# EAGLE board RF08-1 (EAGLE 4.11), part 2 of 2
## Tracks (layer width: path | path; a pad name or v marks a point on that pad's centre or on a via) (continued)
DMA09  (via drill 0.61) (continued)
  Top 0.254: v130.17,77.3 130.17,72.22 128.27,72.22 127,70.95 125.73,70.95 DMA8-11.6 | 50.79,18.89 50.79,20.16 49.52,21.43 49.52,23.96 50.79,25.23 50.79,29.05 IC11.10 50.79,31.59 49.52,32.86 49.52,47.46 50.79,48.73 50.79,51.91 IC10.10 50.79,54.45 49.52,55.72 49.52,69.68 50.79,70.95 50.79,74.77 IC9.10 | 50.79,18.89 50.79,8.73 IC12.10 | v197.48,72.22 197.48,39.84 196.21,38.57 196.21,4.28 194.94,3.01 160.65,3.01 v160.65,15.71 | v95.88,13.81 v90.8,18.89 | v50.16,18.89 50.79,18.89
  Bottom 0.254: v130.17,77.3 147.31,77.3 148.59,76.03 IC6.6 151.12,76.03 154.94,72.22 v197.48,72.22 | v160.65,15.71 160.65,18.89 140.97,18.89 138.43,16.35 118.74,16.35 116.2,13.81 v95.88,13.81 | v90.8,18.89 v50.16,18.89
DMA10  (via drill 0.61)
  Top 0.254: IC12.11 53.34,8.73 52.06,10 52.06,23.96 53.34,25.23 53.34,29.05 IC11.11 53.34,31.59 52.06,32.86 52.06,46.83 53.34,48.09 53.34,51.91 IC10.11 53.34,54.45 52.06,55.72 52.06,73.49 53.34,74.77 IC9.11 | v133.98,79.84 133.98,89.37 133.34,90 v133.34,91.91 | v125.09,91.91 123.19,93.81 123.19,98.26 123.82,98.89 v123.82,109.05 | v116.84,109.05 115.56,107.78 v115.56,104.61 | v95.88,103.97 95.25,103.34 v95.25,79.84
  Bottom 0.254: DMA8-11.2 125.73,81.11 126.36,80.48 130.17,80.48 130.81,79.84 v133.98,79.84 147.31,79.84 148.59,81.11 IC6.4 | v125.09,91.91 v133.34,91.91 | v116.84,109.05 v123.82,109.05 | v115.56,104.61 114.93,105.24 104.77,105.24 103.5,103.97 v95.88,103.97 | v95.25,79.84 94.61,80.48 57.14,80.48 56.51,79.84 54.6,79.84 53.34,78.57 53.34,77.3 IC9.11
DMA11  (via drill 0.61)
  Top 0.254: IC12.12 55.88,8.73 55.88,20.16 54.6,21.43 54.6,27.78 55.88,29.05 IC11.12 55.88,31.59 54.6,32.86 54.6,50.63 | 54.6,50.63 55.88,51.91 IC10.12 | 54.6,50.63 54.6,73.49 55.88,74.77 IC9.12 55.88,77.3 v55.88,81.75 | v121.28,81.11 v121.28,78.57 | v146.68,86.19 143.5,89.37 143.5,97.62 138.43,102.7 v138.43,106.52 | v88.9,82.38 v88.9,107.15
  Bottom 0.254: v121.28,78.57 123.19,78.57 DMA8-11.3 | v121.28,81.11 120.01,82.38 107.95,82.38 107.31,81.75 88.9,81.75 | v55.88,81.75 88.9,81.75 | v146.68,86.19 148.59,86.19 IC6.2 | v138.43,106.52 104.77,106.52 104.14,107.15 v88.9,107.15 | 88.9,81.75 v88.9,82.38
DMA-IN\  (via drill 0.61)
  Top 0.254: 17.14,44.92 15.87,43.65 IC19.1 | 17.14,44.92 17.14,71.59 15.87,72.86 IC18.1 | v25.39,10.63 17.14,18.89 17.14,44.92
  Bottom 0.254: 13.33,72.22 13.33,73.49 13.96,73.49 IC18.1 | 13.33,72.22 13.33,70.32 13.96,69.68 20.32,69.68 21.59,70.95 IC18.19 | v25.39,10.63 84.45,10.63 85.72,11.9 IC41.12 | 13.33,72.22 4.44,72.22 4.44,77.94 13.96,87.46 16.51,87.46 21.59,92.54 24.12,92.54 25.39,93.81 33.02,93.81 37.46,98.26 IC15.4
DMA-OUT\  (via drill 0.61)
  Top 0.254: v88.26,32.86 88.26,19.52 93.98,13.81 IC41.9 | v81.28,69.68 81.91,69.05 81.91,55.72 83.18,54.45 85.09,54.45 85.09,39.84 84.45,39.2 79.37,39.2 79.37,38.57 IC17.19
  Bottom 0.254: 75.56,67.78 74.93,68.41 72.39,68.41 IC16.1 | 75.56,67.78 77.47,65.88 IC16.19 | IC17.1 72.39,40.48 73.02,40.48 74.29,39.2 76.2,39.2 77.47,37.94 IC17.19 79.37,37.3 82.55,34.12 86.99,34.12 v88.26,32.86 | 75.56,67.78 77.47,69.68 v81.28,69.68
DONE  (via drill 0.61)
  Top 0.254: v135.88,31.59 135.25,30.95 135.25,19.52 136.52,18.25 IC39.2 | v128.9,33.49 129.53,34.12 129.53,51.27 v128.9,51.91 | v139.69,51.91 140.97,53.18 140.97,88.73 v140.33,89.37 | v144.78,89.37 146.05,90.64 146.05,119.21 144.78,120.48 IC35.9
  Bottom 0.254: v135.88,31.59 133.98,33.49 v128.9,33.49 | v139.69,51.91 v128.9,51.91 | v144.78,89.37 v140.33,89.37
DRV01\  (via drill 0.61)
  Top 0.254: IC10.22 53.34,69.68 53.97,70.32 53.97,74.13 54.6,74.77 54.6,77.3 53.34,78.57 v53.34,80.48 53.34,90 IC9.22 | v99.69,6.82 107.95,15.08 v107.95,74.13 | v97.79,74.13 v97.79,78.57
  Bottom 0.254: v99.69,6.82 85.72,6.82 84.45,5.55 IC41.4 | v107.95,74.13 v97.79,74.13 | v97.79,78.57 95.25,81.11 56.51,81.11 55.88,80.48 v53.34,80.48
DRV23\  (via drill 0.61)
  Top 0.254: IC11.22 53.34,44.29 53.34,32.86 54.6,31.59 54.6,29.05 53.97,28.41 53.97,24.6 53.34,23.96 IC12.22 53.34,21.43 53.34,10.63 v54.6,9.36 | v86.36,10 90.8,5.55 IC41.7
  Bottom 0.254: v86.36,10 55.24,10 v54.6,9.36
EIE  (via drill 0.61)
  Top 0.254: v171.44,6.18 174.62,9.36 INTENB.6 175.25,8.73 175.25,8.09 180.97,8.09 181.61,8.73 181.61,21.43 184.78,24.6 IC33.2
  Bottom 0.254: v171.44,6.18 147.31,6.18 146.05,7.46 IC39.9
ERROR  (via drill 0.61)
  Top 0.254: v142.24,91.91 142.24,41.74 142.87,41.11 142.87,11.9 144.14,10.63 IC39.10 | v156.21,91.91 156.84,92.54 156.84,116.67 156.21,117.31 v156.21,121.75 156.21,125.56 IC37.2
  Bottom 0.254: v156.21,91.91 v142.24,91.91 | v156.21,121.75 173.99,121.75 IC34.6
EXAD0\  (via drill 0.61)
  Top 0.254: v5.71,74.77 5.71,68.41 7.62,66.51 C35L.34
  Bottom 0.254: v5.71,74.77 6.34,74.77 14.6,83.02 IC38.9
EXAD1\
  Top 0.254: IC38.7 15.87,89.37 17.14,90.64 17.14,94.45 16.51,95.08 6.98,95.08 6.98,74.77 6.34,74.13 6.34,70.32 7.62,69.05 C35L.36
EXAD2\
  Top 0.254: IC38.5 14.6,93.18 8.88,87.46 8.88,72.86 7.62,71.59 C35L.38
F.1  (1 unrouted)
  Top 0.254: IC32.8 186.05,43.65 187.32,44.92 187.32,104.61 186.05,105.88 FIELD.3
F.2  (via drill 0.61)
  Top 0.254: v34.28,89.37 34.28,117.94 33.65,118.58 v33.65,127.47 | v179.06,128.11 180.97,126.2 180.97,117.31 183.51,114.77 183.51,110.96 184.78,109.69 FIELD.2 | v197.48,38.57 198.12,39.2 198.12,71.59 198.75,72.22 198.75,74.13 195.58,77.3 195.58,105.24 v196.21,105.88
  Bottom 0.254: v34.28,89.37 27.3,89.37 24.12,86.19 IC38.13 | v33.65,127.47 35.55,129.38 164.46,129.38 165.09,128.74 173.35,128.74 173.99,128.11 v179.06,128.11 | v197.48,38.57 194.94,38.57 194.31,37.94 IC32.11 | v196.21,105.88 194.31,107.78 188.59,107.78 187.32,109.05 186.69,109.05 FIELD.2
F.3  (via drill 0.61)
  Top 0.254: v28.57,131.28 29.21,130.65 29.21,120.48 26.67,117.94 26.67,95.08 23.49,91.91 IC38.15 | v168.91,130.01 170.18,128.74 v170.18,124.93 | v199.38,43.02 199.38,73.49 200.66,74.77 v200.66,97.62
  Bottom 0.254: v28.57,131.28 60.32,131.28 60.95,131.92 127,131.92 128.27,133.19 128.9,132.55 131.44,132.55 133.34,130.65 164.46,130.65 165.09,131.28 167.63,131.28 v168.91,130.01 | v170.18,124.93 172.08,123.02 190.5,123.02 198.12,115.4 198.12,100.16 | 198.12,100.16 187.96,100.16 186.69,98.89 FIELD.6 | v199.38,43.02 194.31,43.02 IC32.13 | 198.12,100.16 v200.66,97.62
GND  (via drill 0.61)
  Top 0.508: D34L.11 167.63,34.76 167.63,33.49 D34L.9 167.63,32.22 167.63,30.95 D34L.7 167.63,29.68 167.63,28.41 D34L.5 167.63,27.14 167.63,25.87 D34L.3 167.63,24.6 167.63,23.33 D34L.1 168.27,22.7 169.54,22.7 J12.2 170.18,23.33 170.18,24.6 J11.2 170.18,25.87 170.18,27.14 J10.2 170.18,28.41 170.18,29.68 J9.2 170.18,30.95 170.18,32.22 J8.2 170.18,33.49 170.18,34.76 J7.2 170.18,36.03 170.18,37.3 J6.2 169.54,37.94 168.27,37.94 D34L.13 167.63,38.57 167.63,39.84 D34L.15 167.63,41.11 167.63,42.38 D34L.17 167.63,43.65 167.63,44.92 D34L.19 167.63,46.19 167.63,47.46 D34L.21 167.63,48.73 167.63,50 D34L.23 167.63,51.27 167.63,52.54 D34L.25 167.63,53.81 167.63,55.08 D34L.27 167.63,56.35 167.63,57.62 D34L.29 167.63,58.89 167.63,60.16 D34L.31 167.63,61.43 167.63,62.7 D34L.33 167.63,63.97 167.63,65.24 D34L.35 167.63,66.51 167.63,67.78 D34L.37 167.63,69.05 167.63,70.32 D34L.39 | DMA0-3.8 125.09,5.55 126.36,6.82 126.36,13.17 125.09,14.44 DMA0-3.4 | IC8.10 151.12,4.92 156.21,4.92 IC8.11 158.11,5.55 159.38,6.82 159.38,8.09 | 159.38,8.09 158.11,9.36 IC8.13 | 159.38,13.17 158.11,14.44 IC8.15 | 159.38,13.17 159.38,8.09 | 159.38,13.17 159.38,18.25 158.11,19.52 IC8.17 | IC26.8 147.31,97.62 148.59,98.89 148.59,110.32 147.31,111.59 147.31,112.86 IC35.7 147.31,115.4 148.59,116.67 148.59,124.29 147.31,125.56 IC36.8 | IC31.1 187.96,132.55 187.96,133.82 C1.2 | IC37.1 153.66,128.11 153.66,130.65 156.21,133.19 IC37.15 156.21,135.72 156.21,137 166.37,137 167.63,135.72 167.63,133.19 170.81,130.01 170.81,128.74 171.44,128.11 IC37.8 171.44,125.56 172.08,124.93 v172.08,119.21
  Top 0.508: FIELD.4 184.78,103.34 184.78,102.07 FIELD.5 184.78,100.8 183.51,99.53 183.51,95.72 184.78,94.45 FIELD.8 | IC34.7 175.89,118.58 179.06,115.4 179.06,109.05 180.34,107.78 IC40.7 | v170.18,82.38 170.18,84.92 IC20.12 | INTENB.4 170.81,9.36 172.08,9.36 INTENB.5 173.35,10.63 179.7,16.98 INTENB.9 | INTENB.8 180.34,11.27 180.34,16.35 INTENB.9 | INTENB.9 180.34,18.89 180.34,22.06 C36L.1 180.34,23.33 180.34,24.6 C36L.3 180.34,25.87 180.34,27.14 C36L.5 180.34,28.41 180.34,29.68 C36L.7 180.34,30.95 180.34,32.22 C36L.9 180.34,33.49 180.34,34.76 C36L.11 180.34,36.03 180.34,37.3 C36L.13 180.34,38.57 180.34,39.84 C36L.15 180.34,41.11 180.34,42.38 C36L.17 180.34,43.65 180.34,44.92 C36L.19 180.34,46.19 180.34,47.46 C36L.21 180.34,48.73 180.34,50 C36L.23 180.34,51.27 180.34,52.54 C36L.25 180.34,53.81 180.34,55.08 C36L.27 180.34,56.35 180.34,57.62 C36L.29 180.34,58.89 180.34,60.16 C36L.31 180.34,61.43 180.34,62.7 C36L.33 180.34,63.97 180.34,65.24 C36L.35 180.34,66.51 180.34,67.78 C36L.37 180.34,69.05 180.34,70.32 C36L.39 180.34,71.59 180.34,77.3 IC20.7 180.34,79.84 181.61,81.11 181.61,87.46 180.97,88.1 180.97,91.91 180.34,92.54 IC27.7 | IC9.16 66.04,77.3 66.67,77.94 66.67,89.37 67.31,90 67.31,96.35 66.04,97.62 IC14.7 | IC21.8 27.3,126.2 26.03,126.2 IC21.7 25.39,128.11 24.76,128.74 24.76,132.55 24.12,133.19 24.12,135.72 25.39,137 52.06,137 52.06,131.92 55.24,128.74 55.24,109.69 53.34,107.78 IC14.13 53.34,105.24 53.34,100.16 IC14.2 52.7,98.26 51.43,98.26 IC14.1 | IC22.7 50.79,125.56 51.43,124.93 51.43,123.66 52.06,123.02 52.06,111.59 46.98,106.52 46.98,101.43 45.71,100.16 IC15.7
  Top 0.508: IC25.7 124.45,125.56 125.73,124.29 125.73,119.21 127,117.94 127,115.4 IC29.8 | IC35.2 134.62,112.86 134.62,107.78 132.08,105.24 IC26.15 131.44,103.34 131.44,99.53 129.53,97.62 IC26.1 | 80.01,124.29 80.64,123.66 80.64,108.42 80.01,107.78 80.01,101.43 78.73,100.16 IC13.4 | 80.01,124.29 78.73,125.56 IC23.8 | 80.01,124.29 80.01,136.36 97.15,136.36 97.79,135.72 97.79,131.92 101.59,128.11 IC24.7 102.23,126.2 103.5,126.2 IC24.8 104.14,125.56 106.04,123.66 106.04,113.5 100.33,107.78 100.33,90 106.04,84.29 IC5.7 | IC19.10 13.96,20.16 10.15,23.96 10.15,24.6 C35L.1 10.15,25.87 10.15,27.14 C35L.3 10.15,28.41 10.15,29.68 C35L.5 10.15,30.95 10.15,32.22 C35L.7 10.15,33.49 10.15,34.76 C35L.9 10.15,36.03 10.15,37.3 C35L.11 10.15,38.57 10.15,39.84 C35L.13 10.15,41.11 10.15,42.38 C35L.15 10.15,43.65 10.15,44.92 C35L.17 10.15,46.19 10.15,47.46 C35L.19 10.15,48.73 10.15,50 C35L.21 10.15,51.27 10.15,52.54 C35L.23 10.15,53.81 10.15,55.08 C35L.25 10.15,56.35 10.15,57.62 C35L.27 10.15,58.89 10.15,60.16 C35L.29 10.15,61.43 10.15,62.7 C35L.31 10.15,63.97 10.15,65.24 C35L.33 10.15,66.51 10.15,67.78 C35L.35 10.15,69.05 10.15,70.32 C35L.37 10.15,71.59 10.15,72.86 C35L.39 10.15,74.13 10.15,76.03 14.6,80.48 IC38.10 15.87,81.75 17.78,83.65 17.78,106.52 22.86,106.52 24.76,104.61 24.76,98.26 23.49,96.99 IC38.17 | v116.84,74.77 116.84,69.05 D36L.39 116.84,67.78 116.84,66.51 D36L.37 116.84,65.24 116.84,63.97 D36L.35 116.84,62.7 116.84,61.43 D36L.33 116.84,60.16 116.84,58.89 D36L.31 116.84,57.62 116.84,56.35 D36L.29 116.84,55.08 116.84,53.81 D36L.27 116.84,52.54 116.84,51.27 D36L.25 116.84,50 116.84,48.73 D36L.23 116.84,47.46 116.84,46.19 D36L.21 116.84,44.92 116.84,43.65 D36L.19 116.84,42.38 116.84,41.11 D36L.17 116.84,39.84 116.84,38.57 D36L.15 116.84,37.3 116.84,36.03 D36L.13 116.84,34.76 116.84,33.49 D36L.11 116.84,32.22 116.84,30.95 D36L.9 116.84,29.68 116.84,28.41 D36L.7 116.84,27.14 116.84,25.87 D36L.5 116.84,24.6 116.84,23.33 D36L.3 116.84,22.06 116.84,20.79 D36L.1
  Top 0.508: DAR8-11.8 136.52,66.51 135.25,67.78 135.25,74.13 136.52,75.4 DAR8-11.4 | DAR4-7.8 136.52,36.03 135.25,37.3 135.25,43.65 136.52,44.92 DAR4-7.4 | 69.21,11.9 70.48,13.17 70.48,16.98 IC17.10 | 69.21,11.9 66.04,8.73 IC12.16 | 69.21,20.79 69.21,11.9 | 69.21,20.79 69.21,43.65 70.48,44.92 IC16.10 | 80.64,25.87 80.64,24.6 79.37,23.33 IC17.13 | 80.64,25.87 79.37,27.14 IC17.15 | 80.64,25.87 80.64,30.95 79.37,32.22 IC17.17 | IC41.8 93.98,6.18 90.17,10 90.17,15.71 86.36,19.52 D35L.1 86.36,20.79 86.36,22.06 D35L.3 86.36,23.33 86.36,24.6 D35L.5 86.36,25.87 86.36,27.14 D35L.7 86.36,28.41 86.36,29.68 D35L.9 86.36,30.95 86.36,32.22 D35L.11 86.36,33.49 86.36,34.76 D35L.13 86.36,36.03 86.36,37.3 D35L.15 86.36,38.57 86.36,39.84 D35L.17 86.36,41.11 86.36,42.38 D35L.19 86.36,43.65 86.36,44.92 D35L.21 86.36,46.19 86.36,47.46 D35L.23 86.36,48.73 86.36,50 D35L.25 86.36,51.27 86.36,52.54 D35L.27 86.36,53.81 86.36,55.08 D35L.29 86.36,56.35 86.36,57.62 D35L.31 86.36,58.89 86.36,60.16 D35L.33 86.36,61.43 86.36,62.7 D35L.35 86.36,63.97 86.36,65.24 D35L.37 86.36,66.51 86.36,67.78 D35L.39 86.36,69.05 87.62,70.32 87.62,96.35 86.36,97.62 IC13.7 | 69.21,20.79 64.77,20.79 64.77,27.78 66.04,29.05 IC11.16 | IC1.4 99.69,24.6 100.96,24.6 IC1.5 101.59,26.51 102.87,27.78 102.87,40.48 101.59,41.74 IC2.5
  Bottom 0.508: J4.2 169.54,43.02 168.27,43.02 D34L.17 | IC33.10 184.15,4.92 158.75,4.92 IC8.11 | IC8.10 148.59,4.92 147.31,3.65 139.69,3.65 138.43,4.92 IC39.7 135.88,4.92 134.62,3.65 127,3.65 125.73,4.92 DMA0-3.8 123.19,4.92 94.61,4.92 IC41.8 | D34L.1 167,22.7 165.73,21.43 162.56,21.43 161.28,20.16 158.75,20.16 IC8.17 | IC36.8 147.95,126.2 153.03,126.2 IC37.1 | IC31.1 186.69,131.92 185.41,133.19 172.72,133.19 172.08,132.55 158.11,132.55 156.84,133.82 IC37.15 | IC27.7 180.97,93.81 184.15,93.81 FIELD.8 186.69,93.81 191.77,93.81 FIELD.9 | IC40.7 180.97,105.88 182.88,103.97 184.15,103.97 FIELD.4 | IC30.12 191.77,81.11 189.22,83.65 186.69,83.65 IC30.2 184.78,83.02 170.81,83.02 v170.18,82.38 172.08,80.48 178.43,80.48 179.7,79.21 IC20.7 | IC33.6 184.15,15.08 182.24,16.98 180.97,16.98 INTENB.9 | IC32.10 184.15,37.94 180.97,37.94 C36L.13 | IC30.7 184.15,70.95 180.97,70.95 C36L.39 | IC32.6 184.15,48.09 180.97,48.09 C36L.21 | IC32.4 184.15,53.18 180.97,53.18 C36L.25 | v172.08,119.21 173.99,119.21 IC34.7 | J12.2 170.81,22.7 172.08,21.43 178.43,21.43 179.7,22.7 C36L.1 | IC22.7 51.43,126.2 52.7,126.2 IC22.8 | IC15.7 46.35,98.26 50.16,98.26 IC14.1 | 56.51,96.99 57.78,98.26 IC14.4 | 56.51,96.99 55.24,96.99 53.97,98.26 IC14.2 | 56.51,96.99 64.13,96.99 65.4,98.26 IC14.7 66.67,98.26 67.94,96.99 76.83,96.99 78.1,98.26 IC13.4 79.37,99.53 80.64,100.8 84.45,100.8 85.72,99.53 IC13.7 86.99,99.53 108.58,99.53 110.48,101.43 IC28.1 113.03,101.43 115.56,98.89 118.11,98.89 IC28.15 120.65,98.89 122.55,96.99 128.9,96.99 IC26.1 | IC29.8 127.63,114.77 128.9,116.04 132.71,116.04 133.98,114.77 IC35.2
  Bottom 0.508: IC5.7 107.31,83.65 110.48,83.65 IC28.8 | IC23.7 76.83,126.2 78.1,126.2 IC23.8 | IC18.10 13.96,50.63 10.79,50.63 C35L.21 | J13.2 5.71,53.18 6.98,54.45 8.25,54.45 9.52,55.72 C35L.25 10.79,55.72 12.06,55.72 J14.2 | IC38.17 24.12,96.35 26.03,98.26 29.84,98.26 IC15.1 31.11,98.26 32.38,98.26 IC15.2 | IC4.5 102.23,69.05 103.5,70.32 107.31,70.32 108.58,69.05 IC4.8 109.85,69.05 110.48,69.68 114.93,69.68 116.2,68.41 D36L.39 | v116.84,74.77 121.92,74.77 123.19,76.03 DMA8-11.4 | IC6.10 148.59,65.88 147.31,64.6 139.69,64.6 138.43,65.88 DAR8-11.8 135.88,65.88 134.62,64.6 127.63,64.6 126.36,65.88 125.73,65.88 DMA8-11.8 123.19,65.88 117.47,65.88 D36L.37 | IC7.10 148.59,35.4 147.31,34.12 139.69,34.12 138.43,35.4 DAR4-7.8 | IC1.8 109.85,24.6 110.48,23.96 114.93,23.96 116.2,25.23 D36L.5 | DMA4-7.8 123.19,35.4 117.47,35.4 D36L.13 | IC3.5 102.23,56.35 103.5,57.62 107.31,57.62 108.58,56.35 IC3.8 109.85,56.35 110.48,56.98 114.93,56.98 116.2,58.26 D36L.31 | D36L.21 117.47,45.55 123.19,45.55 DMA4-7.4 125.73,45.55 127,44.29 134.62,44.29 135.88,45.55 DAR4-7.4 | IC11.16 66.67,29.68 67.31,29.05 74.29,29.05 75.56,27.78 77.47,27.78 IC17.15 | IC17.13 80.01,22.7 81.28,21.43 84.45,21.43 85.72,22.7 D35L.3 | IC10.16 66.67,52.54 67.31,51.91 80.64,51.91 83.18,49.37 84.45,49.37 85.72,50.63 D35L.25 | 99.69,41.11 99.06,40.48 86.99,40.48 D35L.17 | 99.69,41.11 100.96,42.38 IC2.5 | 99.69,41.11 107.31,41.11 108.58,42.38 IC2.8 109.22,44.29 114.93,44.29 116.2,43.02 D36L.19 | IC19.10 16.51,20.16 18.41,18.25 48.89,18.25 49.52,17.62 69.84,17.62 IC17.10
INT_RQ\  (via drill 0.61)
  Top 0.254: IC39.3 136.52,14.44 135.25,13.17 135.25,9.36 136.52,8.09 IC39.6 | v173.35,37.94 v173.35,56.98 | v141.6,31.59 142.24,30.95 142.24,7.46 144.14,5.55 IC39.8
  Bottom 0.254: IC39.6 138.43,7.46 139.06,6.82 141.6,6.82 143.5,4.92 IC39.8 | v173.35,56.98 167,56.98 165.73,58.26 D34L.30 | v173.35,37.94 172.08,36.66 161.28,36.66 158.11,33.49 151.76,33.49 151.12,32.86 142.87,32.86 v141.6,31.59
IOS\  (via drill 0.61)
  Top 0.254: v163.19,96.35 163.19,74.77 164.46,73.49 164.46,72.22 163.83,71.59 163.83,57.62 165.09,56.35 D34L.28
  Bottom 0.254: v163.19,96.35 180.34,96.35 180.34,100.16 IC27.8
MYDEV\  (via drill 0.61)
  Top 0.254: 97.79,53.18 97.79,45.55 99.06,44.29 IC2.4 99.06,41.74 99.06,38.57 v99.69,37.94 | 97.79,53.18 99.06,54.45 IC3.4 | 97.79,53.18 97.79,65.88 99.06,67.14 IC4.4
  Bottom 0.254: v99.69,37.94 108.58,37.94 PAD8.1
N$1
  Top 0.254: IC1.9 109.22,34.12 109.22,34.76 PAD6.1
N$2  (via drill 0.61)
  Top 0.254: v153.66,119.85 155.57,117.94 v155.57,97.62 | v177.8,97.62 179.06,96.35 179.06,88.73 180.34,87.46 IC20.8
  Bottom 0.254: v153.66,119.85 141.6,119.85 140.33,121.12 IC35.11 | v155.57,97.62 166.37,97.62 167,96.99 177.16,96.99 v177.8,97.62
N$3  (via drill 0.61)
  Top 0.254: v122.55,41.74 122.55,14.44 123.82,13.17 DMA0-3.5
  Bottom 0.254: v122.55,41.74 125.73,41.74 127,43.02 130.81,43.02 DMA4-7.12
N$4
  Top 0.254: SW1.1 10.79,113.5 12.06,113.5 SW1.2 13.33,113.5 14.6,113.5 SW1.3 15.87,113.5 17.14,113.5 SW1.4 18.41,113.5 19.68,113.5 SW1.5 20.95,113.5 22.22,113.5 SW1.6 23.49,113.5 24.76,113.5 SW1.7
  Bottom 0.254: SW1.7 26.03,113.5 27.3,113.5 SW1.8 28.57,113.5 29.84,112.23 114.93,112.23 116.2,113.5 IC29.4
N$5
  Top 0.254: IC1.15 93.98,34.12 93.98,34.76 PAD0.1
N$6
  Top 0.254: IC1.14 96.52,34.12 96.52,34.76 PAD1.1
N$7
  Top 0.254: IC1.13 99.06,34.12 99.06,34.76 PAD2.1
N$8
  Top 0.254: IC1.12 101.59,34.12 101.59,34.76 PAD3.1
N$9
  Top 0.254: IC1.11 104.14,34.12 104.14,34.76 PAD4.1
N$10
  Top 0.254: IC1.10 106.68,34.12 106.68,34.76 PAD5.1
N$11
  Bottom 0.254: IC1.7 106.68,26.51 111.76,31.59 111.76,34.76 PAD7.1
N$12  (via drill 0.61)
  Top 0.254: DAR4-7.14 145.41,48.73 146.68,50 146.68,76.67 145.41,77.94 DAR8-11.14 144.14,79.21 142.87,80.48 142.87,86.19 v143.5,86.83 | v105.41,107.78 105.41,93.81 106.68,92.54 IC5.8 | v130.81,107.78 130.81,101.43 128.27,98.89 128.27,90 130.17,88.1 v130.17,86.83
  Bottom 0.254: v105.41,107.78 106.04,107.15 130.17,107.15 v130.81,107.78 | v130.17,86.83 130.81,87.46 142.87,87.46 v143.5,86.83
N$13  (via drill 0.61)
  Top 0.254: v129.53,70.95 126.36,67.78 126.36,65.24 121.92,60.8 121.92,43.02 123.19,43.02 DMA4-7.5
  Bottom 0.254: v129.53,70.95 131.44,72.86 DMA8-11.12
N$14  (via drill 0.61)
  Top 0.254: v85.09,108.42 85.09,105.24 84.45,104.61 84.45,100.8 83.81,100.16 IC13.6
  Bottom 0.254: IC15.8 46.35,107.15 47.62,108.42 64.13,108.42 65.4,107.15 IC14.8 66.67,107.15 67.94,108.42 v85.09,108.42
N$15
  Bottom 0.254: IC22.5 46.35,127.47 47.62,128.74 109.85,128.74 111.12,127.47 IC25.2
N$16  (via drill 0.61)
  Top 0.254: v112.39,11.9 109.85,14.44 109.85,23.33 110.48,23.96 110.48,46.19 111.76,47.46 111.76,71.59 111.12,72.22 v111.12,74.77
  Bottom 0.254: v112.39,11.9 116.2,11.9 118.11,13.81 120.65,13.81 120.65,11.27 123.19,8.73 125.73,8.73 128.9,11.9 130.17,11.9 130.81,12.54 DMA0-3.12 | v111.12,74.77 113.03,76.67 116.2,76.67 116.84,77.3 128.27,77.3 130.81,74.77 134.62,74.77 135.88,73.49 DAR8-11.5
N$17
  Top 0.254: SW2.1 36.19,113.5 37.46,113.5 SW2.2 38.73,113.5 40,113.5 SW2.3 41.27,113.5 42.54,113.5 SW2.4 43.81,113.5 45.08,113.5 SW2.5 46.35,113.5 47.62,113.5 SW2.6 48.89,113.5 50.16,113.5 SW2.7
  Bottom 0.254: SW2.7 51.43,113.5 52.7,113.5 SW2.8 53.97,114.77 55.24,116.04 117.47,116.04 118.74,114.77 IC29.5
N$19  (via drill 0.61)
  Top 0.254: SW3.1 61.59,113.5 62.86,113.5 SW3.2 64.13,113.5 65.4,113.5 SW3.3 66.67,113.5 67.94,113.5 SW3.4 69.21,113.5 70.48,113.5 SW3.5 71.75,113.5 73.02,113.5 SW3.6 74.29,113.5 75.56,113.5 SW3.7 76.83,113.5 78.1,113.5 SW3.8 78.73,112.86 78.73,111.59 v79.37,110.96 | v116.84,104.61 116.84,107.78 121.92,112.86 IC29.6
  Bottom 0.254: v116.84,104.61 114.93,102.7 92.07,102.7 87.62,107.15 87.62,110.96 v79.37,110.96
N$20  (via drill 0.61)
  Top 0.254: SW4.1 86.99,113.5 88.26,113.5 SW4.2 89.53,113.5 90.8,113.5 SW4.3 92.07,113.5 93.34,113.5 SW4.4 | SW4.5 97.15,113.5 98.42,113.5 SW4.6 99.69,113.5 100.96,113.5 SW4.7 102.23,113.5 103.5,113.5 SW4.8 104.14,115.4 104.14,116.67 v104.77,117.31
  Bottom 0.254: SW4.5 95.88,113.5 94.61,113.5 SW4.4 | v104.77,117.31 105.41,116.67 118.11,116.67 118.74,116.04 122.55,116.04 123.82,114.77 IC29.7
N$21  (via drill 0.61)
  Top 0.254: v72.39,119.85 72.39,124.29 71.12,125.56 IC23.5 | v114.3,118.58 115.56,119.85 115.56,124.29 116.84,125.56 IC25.4
  Bottom 0.254: v72.39,119.85 73.66,118.58 96.52,118.58 97.79,117.31 103.5,117.31 104.77,118.58 108.58,118.58 109.22,119.21 113.66,119.21 v114.3,118.58
N$22  (via drill 0.61)
  Top 0.254: DMA0-3.14 132.71,18.25 133.98,19.52 133.98,46.19 132.71,47.46 DMA4-7.14 132.71,48.73 133.98,50 133.98,76.67 132.71,77.94 DMA8-11.14 | v105.41,79.84 105.41,81.11 104.14,82.38 IC5.6
  Bottom 0.254: v105.41,79.84 129.53,79.84 130.81,78.57 DMA8-11.14
N$23
  Bottom 0.254: IC21.5 20.95,126.2 22.22,124.93 107.31,124.93 108.58,126.2 IC25.1
N$24  (via drill 0.61)
  Top 0.254: v97.79,118.58 97.79,124.29 96.52,125.56 IC24.5 | v118.11,119.85 118.11,124.29 119.38,125.56 IC25.5
  Bottom 0.254: v97.79,118.58 98.42,119.21 107.95,119.21 108.58,119.85 v118.11,119.85
N$25  (via drill 0.61)
  Top 0.254: v128.27,39.2 127.63,39.84 127.63,55.72 128.9,56.98 v128.9,59.52 | v147.95,59.52 151.76,63.34 v151.76,72.22
  Bottom 0.254: v128.27,39.2 133.34,39.2 136.52,42.38 DAR4-7.5 | v128.9,59.52 v147.95,59.52 | v151.76,72.22 147.31,72.22 146.05,73.49 DAR8-11.12
N$26  (via drill 0.61)
  Top 0.254: v144.78,99.53 142.24,102.07 142.24,102.7 IC26.11
  Bottom 0.254: v144.78,99.53 146.68,99.53 148.59,97.62 151.76,97.62 154.3,95.08 163.83,95.08 164.46,94.45 IC27.1
N$27  (via drill 0.61)
  Top 0.254: v116.84,92.54 117.47,93.18 117.47,94.45 118.11,95.08 121.28,95.08 121.28,110.96 123.19,112.86 v123.19,117.94 | v134.62,117.94 135.88,119.21 135.88,130.65 138.43,133.19 138.43,135.72 140.33,137.63 172.72,137.63 172.72,119.85 173.35,119.21 173.35,118.58 176.53,115.4 176.53,103.97 177.8,102.7 IC27.9
  Bottom 0.254: v116.84,92.54 114.3,92.54 113.03,93.81 IC28.4 | v123.19,117.94 131.44,117.94 132.08,118.58 133.98,118.58 v134.62,117.94
N$28  (via drill 0.61)
  Top 0.254: v162.56,107.15 163.19,107.78 163.19,126.2 IC37.5
  Bottom 0.254: v162.56,107.15 164.46,107.15 IC40.1
N$29
  Top 0.254: RA.2 198.12,119.85 198.12,121.12 RB.1 198.12,122.39 199.38,123.66 199.38,125.56 196.21,128.74 IC31.7
N$30
  Top 0.254: IC34.2 174.62,132.55 174.62,133.82 IC34.1 | RL.2 185.41,128.74 186.69,127.47 186.69,126.83 IC31.3
  Bottom 0.254: IC34.2 176.53,131.92 177.8,130.65 184.78,130.65 185.41,130.01 RL.2
N$31  (via drill 0.61)
  Top 0.254: v179.06,104.61 179.06,100.16 176.53,97.62 176.53,88.73 175.25,87.46 IC20.10 | v150.49,103.97 v150.49,121.12 | v146.05,124.93 146.05,128.11 v142.24,131.92 | v133.34,131.92 130.81,131.92 130.81,135.72 130.17,136.36 107.31,136.36 v107.31,122.39 | v95.25,119.85 95.25,105.88 99.06,102.07 99.06,92.54 IC5.11
  Bottom 0.254: v179.06,104.61 178.43,103.97 v150.49,103.97 | v150.49,121.12 146.68,124.93 v146.05,124.93 | v142.24,131.92 v133.34,131.92 | v107.31,122.39 104.77,119.85 v95.25,119.85
N$32
  Top 0.254: RB.2 188.59,121.75 189.86,123.02 189.86,127.47 188.59,128.74 IC31.2
  Bottom 0.254: 191.77,129.38 194.31,126.83 IC31.6 | 191.77,129.38 189.22,129.38 IC31.2 | 191.77,129.38 193.03,129.38 193.03,133.82 C1.1
N$33  (via drill 0.61)
  Top 0.254: v161.92,108.42 162.56,109.05 162.56,131.92 163.83,133.19 IC37.12
  Bottom 0.254: v161.92,108.42 168.27,108.42 169.54,107.15 IC40.3
N$34
  Top 0.254: IC31.5 196.84,124.29 197.48,124.29 C2.2
N$53
  Bottom 0.254: SW1.16 10.79,121.12 12.06,119.85 15.87,119.85 16.51,120.48 16.51,126.2 17.14,126.2 IC21.4
N$54
  Top 0.254: SW1.15 12.69,123.02 15.23,125.56 IC21.3
N$55
  Bottom 0.254: SW1.14 15.23,123.02 12.69,125.56 IC21.2
N$56
  Top 0.254: IC21.1 10.15,125.56 11.42,124.29 11.42,120.48 12.06,119.85 17.14,119.85 17.14,121.12 SW1.13
N$57
  Bottom 0.254: SW1.11 22.22,122.39 19.05,125.56 19.05,131.28 10.79,131.28 8.88,133.19 8.88,136.36 13.33,136.36 14.6,135.09 IC21.14
N$58
  Top 0.254: SW1.10 25.39,123.02 24.12,124.29 24.12,130.65 21.59,133.19 21.59,135.72 20.95,136.36 17.78,136.36 17.78,135.72 IC21.13
N$59
  Top 0.254: SW1.9 27.3,121.12 26.03,119.85 21.59,119.85 21.59,131.92 20.32,133.19 IC21.12
N$60
  Top 0.254: SW1.12 19.68,122.39 16.51,125.56 16.51,129.38 12.69,133.19 IC21.15
N$61
  Top 0.254: SW2.16 36.19,121.12 37.46,119.85 41.9,119.85 41.9,124.29 43.17,125.56 IC22.4
N$62
  Top 0.254: SW2.15 38.09,123.02 40.63,125.56 IC22.3
N$63
  Top 0.254: SW2.14 40.63,123.02 41.27,123.66 41.27,124.93 41.9,125.56 41.9,128.11 41.27,128.74 38.09,128.74 38.09,128.11 IC22.2
N$64
  Top 0.254: IC22.1 35.55,128.11 36.19,128.74 36.19,132.55 36.82,133.19 36.82,135.72 37.46,136.36 39.36,136.36 39.36,133.19 44.45,128.11 44.45,124.29 43.17,123.02 SW2.13
N$65
  Top 0.254: SW2.11 48.25,123.02 46.98,124.29 46.98,128.11 41.27,133.82 IC22.14
N$66
  Top 0.254: SW2.10 50.79,123.02 49.52,124.29 49.52,128.11 43.81,133.82 IC22.13
N$67
  Top 0.254: SW2.9 53.34,123.02 52.06,124.29 52.06,128.11 46.35,133.82 IC22.12
N$68
  Top 0.254: SW3.16 60.95,120.48 61.59,119.85 61.59,119.21 67.31,119.21 67.31,124.29 68.58,125.56 IC23.4
N$69
  Top 0.254: SW3.15 63.49,123.02 66.04,125.56 IC23.3
N$70
  Top 0.254: SW3.14 65.4,121.12 64.13,119.85 62.22,119.85 62.22,124.29 63.49,125.56 IC23.2
N$71
  Top 0.254: IC23.1 61.59,127.47 62.86,128.74 69.84,128.74 69.84,124.29 68.58,123.02 SW3.13
N$72
  Top 0.254: SW3.11 74.29,121.12 75.56,119.85 80.01,119.85 80.01,123.02 77.47,125.56 77.47,128.11 72.39,133.19 72.39,135.72 71.75,136.36 66.04,136.36 66.04,135.72 IC23.14
N$73
  Top 0.254: SW3.10 75.56,122.39 72.39,125.56 72.39,129.38 68.58,133.19 IC23.13
N$74
  Top 0.254: SW3.9 78.1,122.39 74.93,125.56 74.93,129.38 71.12,133.19 IC23.12
N$75
  Top 0.254: SW4.16 86.36,123.02 87.62,124.29 87.62,128.11 88.26,128.74 93.98,128.74 93.98,128.11 IC24.4
N$76
  Top 0.254: SW4.15 88.9,123.02 91.44,125.56 IC24.3
N$77
  Top 0.254: SW4.14 90.8,121.12 89.53,119.85 87.62,119.85 87.62,123.02 88.9,124.29 88.9,125.56 IC24.2
N$78
  Top 0.254: IC24.1 86.36,125.56 85.09,124.29 85.09,120.48 86.36,119.21 93.34,119.21 93.34,121.12 SW4.13
N$79  (via drill 0.61)
  Top 0.254: v95.25,123.66 95.25,129.38 91.44,133.19 IC24.14
  Bottom 0.254: v95.25,123.66 97.15,123.66 98.42,122.39 SW4.11
N$80
  Top 0.254: SW4.10 100.96,122.39 97.79,125.56 97.79,129.38 93.98,133.19 IC24.13
N$81
  Top 0.254: SW4.9 103.5,122.39 100.33,125.56 100.33,128.11 96.52,131.92 96.52,133.19 IC24.12
N$82  (via drill 0.61)
  Top 0.254: v96.52,117.31 96.52,120.48 SW4.12 | v86.99,117.31 84.45,119.85 84.45,128.74 88.9,133.19 IC24.15
  Bottom 0.254: v86.99,117.31 v96.52,117.31
N$83
  Top 0.254: SW3.12 70.48,121.12 67.94,118.58 59.68,118.58 59.68,128.11 63.49,131.92 63.49,133.19 IC23.15
N$84
  Top 0.254: SW2.12 45.08,121.12 43.17,119.21 34.28,119.21 34.28,123.02 36.82,125.56 36.82,131.92 38.09,133.19 IC22.15
PBIT  (via drill 0.61)
  Top 0.254: v5.71,76.67 3.81,74.77 3.81,27.14 29.21,1.74 76.2,1.74 76.2,2.38 77.47,3.65 77.47,6.18 80.01,8.73 80.01,13.81 78.73,15.08 78.73,16.98 IC17.11
  Bottom 0.254: v5.71,76.67 13.96,84.92 16.51,84.92 21.59,90 24.12,90 27.3,93.18 33.65,93.18 34.92,94.45 39.36,94.45 39.36,100.16 40,100.8 61.59,100.8 62.86,99.53 IC14.6
PCA
  Top 0.254: IC34.3 176.53,129.38 177.8,130.65 190.5,130.65 190.5,76.03 191.77,74.77 194.94,74.77 194.94,65.24 191.13,61.43 191.13,15.71 186.05,10.63 IC33.8
  Bottom 0.254: IC39.5 138.43,10 139.69,8.73 161.28,8.73 161.92,8.09 182.24,8.09 184.15,10 IC33.8
PER  (via drill 0.61)
  Top 0.254: v182.88,60.8 181.61,62.06 v181.61,73.49
  Bottom 0.254: v182.88,60.8 184.78,58.89 IC32.2 | v181.61,73.49 184.15,76.03 IC30.5
PER\
  Bottom 0.254: IC30.6 186.69,73.49 190.5,77.3 194.31,77.3 201.93,84.92 201.93,125.56 177.8,125.56 176.53,126.83 IC34.4
PIE  (via drill 0.61)
  Top 0.254: 187.96,8.73 194.94,8.73 194.94,51.27 193.67,52.54 IC32.17 | 187.96,8.73 184.15,8.73 183.51,8.09 183.51,4.92 171.44,4.92 168.91,7.46 168.91,11.9 167,11.9 165.73,10.63 INTENB.2 | v139.69,5.55 139.69,10 137.79,11.9 IC39.4 | v133.98,6.18 134.62,5.55 134.62,3.65 135.25,3.01 159.38,3.01 v159.38,3.65 | v187.96,4.92 187.96,8.73
  Bottom 0.254: v139.69,5.55 139.06,6.18 v133.98,6.18 | v159.38,3.65 186.69,3.65 v187.96,4.92
PROTECT
  Bottom 0.254: IC25.6 122.55,126.2 123.82,124.93 132.71,124.93 133.98,126.2 IC36.3
SETPER\  (via drill 0.61)
  Top 0.254: v81.28,96.35 82.55,97.62 v82.55,133.82 | v177.8,129.38 177.8,119.21 182.88,114.13 182.88,91.91 183.51,91.27 183.51,80.48 184.78,79.21 IC30.4
  Bottom 0.254: v81.28,96.35 43.17,96.35 41.27,98.26 IC15.5 | v82.55,133.82 85.09,136.36 99.69,136.36 100.33,135.72 100.33,132.55 125.09,132.55 128.9,136.36 142.87,136.36 143.5,135.72 143.5,131.92 172.72,131.92 173.99,130.65 176.53,130.65 v177.8,129.38
SETWLS\  (via drill 0.61)
  Top 0.254: v194.94,112.86 194.94,77.94 193.67,76.67 IC30.10 | v143.5,116.04 143.5,124.29 144.78,125.56 IC36.7
  Bottom 0.254: v194.94,112.86 190.5,117.31 158.75,117.31 157.47,116.04 v143.5,116.04
SKIP\  (via drill 0.61)
  Top 0.254: 113.03,109.05 113.03,108.42 113.66,107.78 113.66,100.8 112.39,99.53 IC28.2 | 113.03,109.05 111.76,110.32 110.48,110.32 110.48,105.88 109.22,104.61 R1.1 | v165.09,130.01 165.09,125.56 166.37,124.29 166.37,109.05 167.63,107.78 IC40.2 | v115.56,130.65 113.03,128.11 113.03,109.05
  Bottom 0.254: 170.81,104.61 169.54,104.61 168.27,105.88 IC40.2 | 170.81,104.61 172.08,105.88 IC40.4 | 170.81,104.61 175.89,104.61 177.16,105.88 IC40.6 | v165.09,130.01 116.2,130.01 v115.56,130.65
START\  (via drill 0.61)
  Top 0.254: 130.17,38.57 130.17,11.9 131.44,10.63 DMA0-3.11 | 130.17,38.57 131.44,39.84 DMA4-7.11 | 130.17,38.57 130.17,69.05 131.44,70.32 DMA8-11.11 | v99.06,80.48 99.06,81.11 97.15,83.02 IC5.3 | v119.38,78.57 120.65,77.3 v120.65,70.32
  Bottom 0.254: v99.06,80.48 100.96,78.57 114.3,78.57 114.93,79.21 118.74,79.21 v119.38,78.57 | v120.65,70.32 121.28,69.68 129.53,69.68 130.81,70.95 DMA8-11.11
VCC  (via drill 0.61)
  Top 0.508: v132.71,55.72 132.71,53.81 DMA4-7.16 | v168.91,59.52 170.18,58.26 170.18,53.81 J1.2 170.18,52.54 170.18,51.27 J2.2 170.18,50 170.18,48.73 J3.2 170.18,47.46 168.91,46.19 168.91,42.38 170.18,41.11 J5.2 170.18,39.84 171.44,38.57 171.44,21.43 168.91,18.89 168.91,16.35 165.09,12.54 162.56,12.54 162.56,16.35 INTENB.16 162.56,18.89 161.28,20.16 161.28,31.59 160.65,32.22 158.11,32.22 158.11,28.41 IC8.20 | v145.41,56.98 145.41,53.81 DAR4-7.16 | v200.66,35.4 v200.66,54.45 | v132.71,86.19 132.71,84.29 DMA8-11.16 | v144.78,86.19 144.78,84.29 DAR8-11.16 | v165.09,82.38 165.09,84.92 IC20.14 | 109.22,133.19 107.95,131.92 107.95,124.29 109.22,123.02 IC29.16 | IC25.14 109.22,133.19 | IC28.16 119.38,102.07 119.38,103.34 R1.2 | 130.81,119.21 129.53,117.94 129.53,105.24 IC26.16 | 130.81,119.21 132.08,120.48 IC35.14 | 130.81,119.21 130.81,128.11 130.17,128.74 130.17,132.55 129.53,133.19 IC36.16 128.9,133.82 128.9,132.55 111.12,132.55 109.85,133.82 IC25.14 | IC27.14 165.09,102.7 163.83,103.97 163.83,111.59 165.09,112.86 IC40.14 | RA.1 187.32,119.21 186.05,119.21 RL.1 185.41,119.85 185.41,121.75 187.32,123.66 IC31.4 | C2.1 198.12,130.01 196.84,131.28 196.84,131.92 IC31.8 194.94,131.28 191.77,128.11 191.77,112.86 192.4,112.23 FIELD.16 192.4,110.96 191.13,109.69 191.13,88.1 192.4,86.83 IC30.14 | IC35.10 142.24,123.02 140.97,124.29 140.97,135.72 141.6,136.36 153.66,136.36 153.66,135.72 IC37.16 | v179.06,59.52 179.06,87.46 178.43,88.1 177.16,88.1 176.53,87.46 176.53,84.92 173.99,82.38 173.99,81.11 172.72,79.84 IC20.4 | v75.56,40.48 75.56,14.44 76.2,13.81 IC41.16
  Top 0.508: IC12.32 27.94,23.96 28.57,24.6 28.57,28.41 29.21,29.05 29.21,31.59 27.94,32.86 27.94,44.29 IC11.32 27.94,46.83 28.57,47.46 28.57,51.27 29.21,51.91 29.21,54.45 28.57,55.08 28.57,67.78 IC10.32 27.94,69.68 29.21,70.95 29.21,77.3 27.94,78.57 | 27.94,78.57 23.49,74.13 IC18.20 | 27.94,78.57 27.94,90 IC9.32 27.94,92.54 v27.94,100.8 | IC3.16 91.44,62.06 91.44,58.89 92.7,57.62 92.7,53.18 91.44,51.91 IC2.16 91.44,49.37 92.7,48.09 92.7,35.4 91.44,34.12 IC1.16 | IC16.20 78.1,69.05 78.1,75.4 v77.47,76.03 76.2,77.3 76.2,97.62 IC13.3 76.2,100.16 74.93,101.43 74.93,108.42 73.02,108.42 71.75,107.15 IC13.14 | v33.02,130.01 35.55,132.55 35.55,133.19 IC22.16 | v60.95,130.65 60.95,133.19 IC23.16 | IC24.16 86.36,133.19 v83.81,130.65 83.81,114.13 87.62,110.32 91.44,110.32 v91.44,102.07 91.44,92.54 IC5.14 | v54.6,102.07 54.6,101.43 55.88,100.16 IC14.3 | v50.79,102.07 50.79,105.24 IC14.14 | 109.22,133.19 v109.22,130.65 | IC25.14 109.22,133.19
  Bottom 0.508: v132.71,55.72 133.34,55.08 141.6,55.08 143.5,53.18 DAR4-7.16 | v145.41,56.98 152.4,56.98 153.66,58.26 156.21,58.26 IC7.20 158.75,58.26 160.02,59.52 v168.91,59.52 v179.06,59.52 | DMA0-3.16 133.34,22.7 134.62,21.43 142.24,21.43 143.5,20.16 IC39.14 145.41,20.79 148.59,23.96 151.12,23.96 151.76,24.6 153.03,24.6 156.21,27.78 IC8.20 | INTENB.16 162.56,18.89 163.83,20.16 181.61,20.16 182.88,18.89 195.58,18.89 195.58,25.23 193.67,27.14 IC33.20 193.67,28.41 v200.66,35.4 | v200.66,54.45 194.31,60.8 IC32.20 | v132.71,86.19 133.34,85.56 144.14,85.56 v144.78,86.19 146.05,87.46 154.94,87.46 156.21,88.73 IC6.20 158.75,88.73 162.56,88.73 163.19,88.1 | 163.19,88.1 164.46,86.83 IC20.14 | v165.09,82.38 168.27,82.38 169.54,81.11 170.18,81.11 172.08,79.21 IC20.4 | 163.19,88.1 189.86,88.1 191.77,86.19 IC30.14 | IC26.16 128.9,103.97 120.01,103.97 R1.2 | IC35.10 141.6,122.39 140.33,123.66 133.98,123.66 132.71,122.39 IC35.14 | IC37.16 154.3,135.09 155.57,136.36 179.7,136.36 181.61,134.46 IC34.14 184.15,134.46 185.41,135.72 193.67,135.72 194.94,134.46 194.94,132.55 IC31.8 | RA.1 188.59,119.21 189.86,117.94 191.77,117.94 196.21,113.5 196.21,111.59 194.31,111.59 FIELD.16 191.77,111.59 190.5,112.86 184.15,112.86 183.51,112.23 167,112.23 165.73,113.5 IC40.14 | v75.56,40.48 77.47,40.48 IC17.20 | IC19.20 24.12,43.02 26.03,44.92 27.3,44.92 IC11.32 | IC41.16 75.56,13.17 74.29,14.44 18.41,14.44 13.33,19.52 13.33,21.43 27.94,21.43 IC12.32 | IC1.16 92.07,32.22 97.15,27.14 102.23,27.14 103.5,25.87 IC1.6 | IC16.20 80.01,68.41 81.28,67.14 87.62,67.14 90.8,63.97 IC3.16
  Bottom 0.508: v77.47,76.03 90.8,76.03 IC4.16 | IC21.16 10.79,133.82 12.69,131.92 26.03,131.92 27.94,130.01 v33.02,130.01 60.32,130.01 v60.95,130.65 v83.81,130.65 v109.22,130.65 | IC15.14 29.84,106.52 20.32,106.52 19.68,105.88 19.68,103.97 21.59,103.97 IC38.20 24.12,103.97 27.3,100.8 v27.94,100.8 33.65,100.8 34.92,99.53 IC15.3 36.19,99.53 38.09,101.43 50.79,101.43 | 50.79,101.43 53.97,101.43 v54.6,102.07 73.02,102.07 | 50.79,101.43 v50.79,102.07 | 73.02,102.07 75.56,99.53 IC13.3 | v91.44,102.07 73.02,102.07
WE\  (via drill 0.61)
  Top 0.254: IC12.29 35.55,23.96 36.82,25.23 36.82,31.59 36.19,32.22 36.19,44.92 IC11.29 35.55,46.83 36.82,48.09 36.82,54.45 35.55,55.72 35.55,67.14 IC10.29 35.55,69.68 36.82,70.95 36.82,88.73 35.55,90 IC9.29 | v121.92,124.29 120.65,123.02 v120.65,119.21 | v109.22,117.94 106.68,115.4 v106.68,94.45
  Bottom 0.254: v121.92,124.29 137.16,124.29 139.06,126.2 IC36.5 | v120.65,119.21 118.74,117.31 109.85,117.31 v109.22,117.94 | v106.68,94.45 106.04,93.81 80.64,93.81 73.66,86.83 40,86.83 36.19,90.64 IC9.29
WLS
  Top 0.254: IC33.4 186.05,20.79 190.5,25.23 190.5,70.95 192.4,72.86 IC30.9
WLS\  (via drill 0.61)
  Top 0.254: v200.66,70.95 201.93,72.22 201.93,128.11 194.31,135.72 173.35,135.72 173.35,126.2 174.62,124.93 IC34.5
  Bottom 0.254: v200.66,70.95 194.31,70.95 IC30.8
WRITING  (via drill 0.61)
  Top 0.254: 135.88,116.67 133.98,116.67 133.98,117.31 133.34,117.94 133.34,124.29 132.08,125.56 IC36.2 | 135.88,116.67 139.69,116.67 141.6,114.77 IC35.5 | IC9.24 48.25,90 49.52,88.73 v49.52,74.13 49.52,70.95 48.25,69.68 IC10.24 48.25,67.14 48.89,66.51 48.89,55.08 49.52,54.45 49.52,48.73 48.25,47.46 48.25,46.83 IC11.24 48.25,44.29 48.25,32.86 49.52,31.59 49.52,25.23 48.25,23.96 IC12.24 48.25,21.43 48.25,16.98 v49.52,15.71 | IC41.13 83.18,11.9 81.91,11.9 IC41.14 81.28,13.81 v80.01,15.08 | 135.88,116.67 135.88,100.16 133.34,97.62 133.34,93.18 131.44,91.27 131.44,85.56 128.9,83.02 v128.9,73.49
  Bottom 0.254: v80.01,15.08 79.37,15.71 v49.52,15.71 | v128.9,73.49 127.63,72.22 122.55,72.22 121.92,72.86 114.3,72.86 112.39,70.95 111.12,70.95 109.22,72.86 85.72,72.86 84.45,74.13 v49.52,74.13

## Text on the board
Bottom: RF08 | vrs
